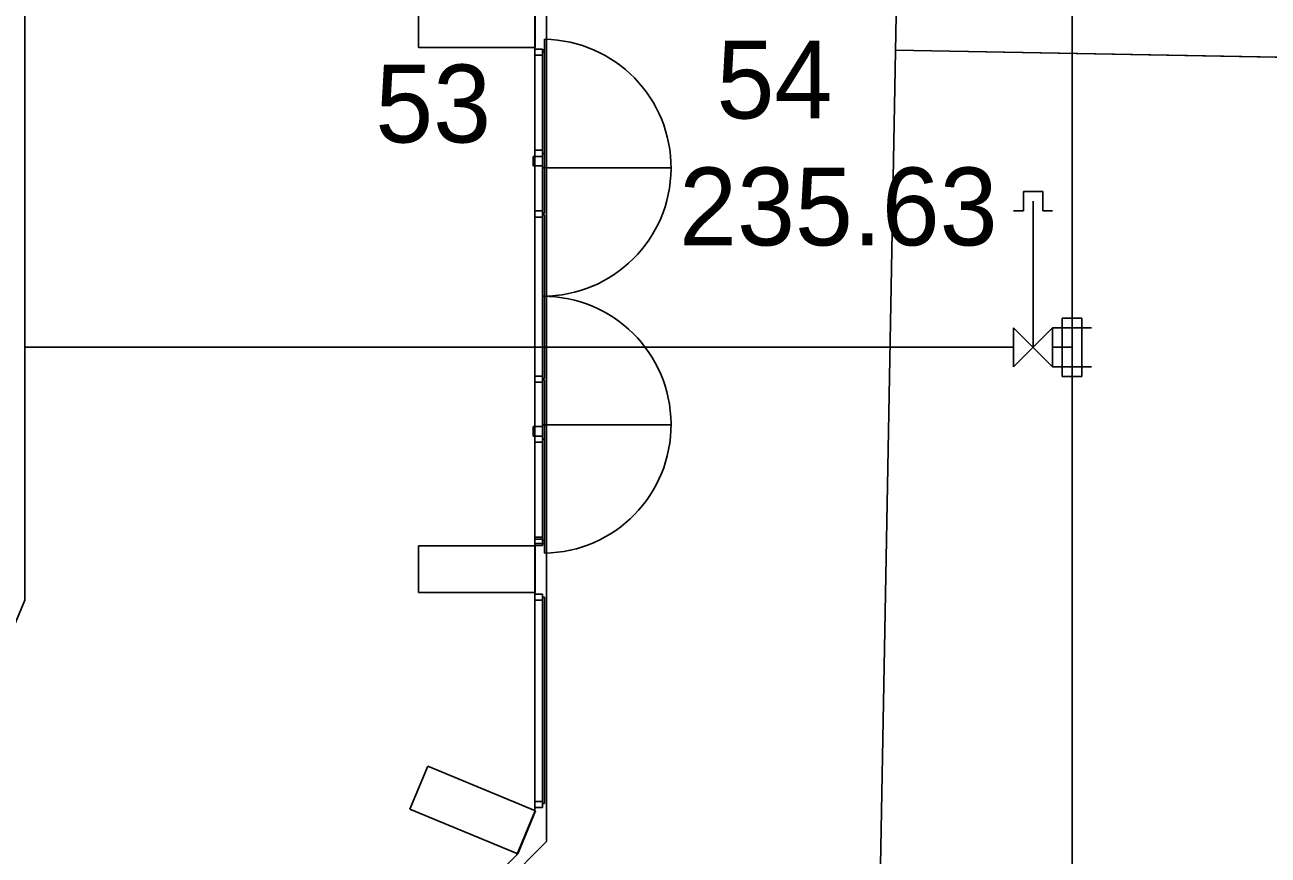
# Model space of a CAD drawing. Extents: x -264234 to -263604, y -1242346 to -1242049.
# Drawn here: x -263801.59 to -263785.62, y -1242227.55 to -1242216.89 of the extents above; entities that cross this region are included whole.
import ezdxf

# ---------------------------------------------------------------- set-up
doc = ezdxf.new("R2010")
doc.units = 0
for name, color, linetype in [('KFA_BODY_CISLO', 7, 'Continuous'), ('KFA_BODY_VYSKA', 7, 'Continuous'), ('KFA_JESTV_IS_DSP_-_KANAL_DAZD', 7, 'Continuous'), ('KFA_SITUACIA_DSP', 7, 'Continuous'), ('KFA_SO_40-2-II_DK_PRIPOJKY_UV_PROJEKT', 7, 'Continuous')]:
    doc.layers.add(name, color=color, linetype=linetype)

msp = doc.modelspace()

# ---------------------------------------------------------------- linework, layer by layer
at = {"layer": 'KFA_JESTV_IS_DSP_-_KANAL_DAZD'}
msp.add_line((-263790.323, -1242212.531), (-263791.054, -1242252.363), dxfattribs=at)
at = {"layer": 'KFA_SITUACIA_DSP'}
for p, q in [((-263788.143, -1242250.14), (-263788.143, -1242082.64)), ((-263795.043, -1242101.769), (-263795.043, -1242226.995)), ((-263796.538, -1242216.582), (-263796.538, -1242217.182)), ((-263795.038, -1242217.182), (-263795.038, -1242216.582)), ((-263796.538, -1242217.182), (-263795.038, -1242217.182)), ((-263795.043, -1242217.282), (-263795.043, -1242217.202)), ((-263795.043, -1242217.202), (-263794.943, -1242217.202)), ((-263795.043, -1242217.282), (-263795.043, -1242217.202)), ((-263795.043, -1242217.202), (-263794.943, -1242217.202)), ((-263794.943, -1242217.202), (-263794.943, -1242217.242)), ((-263794.943, -1242217.202), (-263794.943, -1242217.242)), ((-263794.918, -1242217.212), (-263794.943, -1242217.212)), ((-263794.943, -1242217.212), (-263794.943, -1242219.312)), ((-263794.918, -1242217.077), (-263794.918, -1242218.727)), ((-263794.918, -1242219.312), (-263794.918, -1242217.212)), ((-263781.818, -1242217.375), (-263790.409, -1242217.218)), ((-263794.943, -1242217.282), (-263795.043, -1242217.282)), ((-263794.943, -1242217.282), (-263795.043, -1242217.282)), ((-263794.943, -1242217.242), (-263794.943, -1242217.282)), ((-263794.918, -1242217.242), (-263794.943, -1242217.242)), ((-263794.943, -1242217.242), (-263794.943, -1242218.542)), ((-263794.943, -1242217.242), (-263794.943, -1242217.282)), ((-263794.918, -1242218.542), (-263794.918, -1242217.242)), ((-263795.063, -1242218.702), (-263795.063, -1242218.582)), ((-263795.063, -1242218.582), (-263794.943, -1242218.582)), ((-263794.943, -1242218.502), (-263795.043, -1242218.502)), ((-263795.043, -1242218.502), (-263795.043, -1242218.582)), ((-263795.043, -1242218.582), (-263794.943, -1242218.582)), ((-263794.943, -1242218.542), (-263794.943, -1242218.502)), ((-263794.943, -1242218.542), (-263794.918, -1242218.542)), ((-263794.943, -1242218.582), (-263794.943, -1242218.542)), ((-263794.943, -1242218.582), (-263794.943, -1242218.702)), ((-263794.943, -1242218.702), (-263795.063, -1242218.702)), ((-263794.943, -1242218.702), (-263794.943, -1242218.727)), ((-263794.943, -1242218.727), (-263793.293, -1242218.727)), ((-263788.768, -1242219.032), (-263788.768, -1242219.282)), ((-263788.518, -1242219.032), (-263788.768, -1242219.032)), ((-263788.518, -1242219.282), (-263788.518, -1242219.032)), ((-263795.043, -1242219.362), (-263795.043, -1242219.282)), ((-263795.043, -1242219.282), (-263794.943, -1242219.282)), ((-263794.943, -1242219.282), (-263794.943, -1242219.322)), ((-263788.768, -1242219.282), (-263788.893, -1242219.282)), ((-263788.643, -1242221.032), (-263788.643, -1242219.157)), ((-263788.518, -1242219.282), (-263788.393, -1242219.282)), ((-263794.943, -1242219.362), (-263795.043, -1242219.362)), ((-263794.943, -1242219.312), (-263794.918, -1242219.312)), ((-263794.943, -1242219.322), (-263794.943, -1242219.362)), ((-263794.943, -1242221.432), (-263794.943, -1242219.332)), ((-263794.943, -1242219.332), (-263794.918, -1242219.332)), ((-263794.918, -1242219.332), (-263794.918, -1242221.432)), ((-263788.268, -1242220.657), (-263788.268, -1242221.407)), ((-263788.018, -1242220.657), (-263788.268, -1242220.657)), ((-263788.018, -1242221.407), (-263788.018, -1242220.657)), ((-263788.893, -1242220.782), (-263788.893, -1242221.282)), ((-263788.393, -1242221.282), (-263788.893, -1242220.782)), ((-263788.893, -1242221.282), (-263788.393, -1242220.782)), ((-263788.393, -1242220.782), (-263788.393, -1242221.282)), ((-263788.393, -1242220.782), (-263787.893, -1242220.782)), ((-263801.593, -1242221.032), (-263800.593, -1242221.032)), ((-263788.893, -1242221.032), (-263800.593, -1242221.032)), ((-263788.143, -1242221.032), (-263788.393, -1242221.032)), ((-263788.393, -1242221.032), (-263788.143, -1242221.032)), ((-263788.393, -1242221.282), (-263787.893, -1242221.282)), ((-263795.043, -1242221.482), (-263795.043, -1242221.402)), ((-263795.043, -1242221.402), (-263794.943, -1242221.402)), ((-263794.943, -1242221.482), (-263795.043, -1242221.482)), ((-263794.943, -1242221.402), (-263794.943, -1242221.492)), ((-263794.918, -1242221.432), (-263794.943, -1242221.432)), ((-263794.918, -1242221.452), (-263794.943, -1242221.452)), ((-263794.943, -1242221.452), (-263794.943, -1242223.552)), ((-263794.943, -1242221.492), (-263794.943, -1242221.482)), ((-263794.918, -1242223.552), (-263794.918, -1242221.452)), ((-263788.268, -1242221.407), (-263788.018, -1242221.407)), ((-263794.943, -1242222.052), (-263795.063, -1242222.052)), ((-263795.063, -1242222.052), (-263795.063, -1242222.172)), ((-263794.943, -1242222.052), (-263794.943, -1242222.027)), ((-263794.943, -1242222.027), (-263793.293, -1242222.027)), ((-263794.943, -1242222.172), (-263794.943, -1242222.052)), ((-263794.918, -1242223.677), (-263794.918, -1242222.027)), ((-263795.063, -1242222.172), (-263794.943, -1242222.172)), ((-263795.043, -1242222.252), (-263795.043, -1242222.172)), ((-263795.043, -1242222.172), (-263794.943, -1242222.172)), ((-263794.943, -1242222.252), (-263795.043, -1242222.252)), ((-263794.943, -1242222.172), (-263794.943, -1242222.212)), ((-263794.943, -1242223.512), (-263794.943, -1242222.212)), ((-263794.943, -1242222.212), (-263794.918, -1242222.212)), ((-263794.943, -1242222.212), (-263794.943, -1242222.252)), ((-263794.918, -1242222.212), (-263794.918, -1242223.512)), ((-263795.038, -1242223.582), (-263796.538, -1242223.582)), ((-263796.538, -1242223.582), (-263796.538, -1242224.182)), ((-263794.943, -1242223.472), (-263795.043, -1242223.472)), ((-263795.043, -1242223.472), (-263795.043, -1242223.552)), ((-263794.943, -1242223.497), (-263795.043, -1242223.497)), ((-263795.043, -1242223.497), (-263795.043, -1242223.577)), ((-263795.043, -1242223.552), (-263794.943, -1242223.552)), ((-263795.043, -1242223.577), (-263794.943, -1242223.577)), ((-263795.038, -1242224.182), (-263795.038, -1242223.582)), ((-263794.943, -1242223.512), (-263794.943, -1242223.472)), ((-263794.943, -1242223.537), (-263794.943, -1242223.497)), ((-263794.918, -1242223.512), (-263794.943, -1242223.512)), ((-263794.943, -1242223.552), (-263794.943, -1242223.512)), ((-263794.943, -1242223.577), (-263794.943, -1242223.537)), ((-263794.943, -1242223.552), (-263794.918, -1242223.552)), ((-263796.538, -1242224.182), (-263795.038, -1242224.182)), ((-263795.043, -1242224.282), (-263795.043, -1242224.202)), ((-263795.043, -1242224.202), (-263794.943, -1242224.202)), ((-263794.943, -1242224.202), (-263794.943, -1242224.242)), ((-263794.918, -1242224.242), (-263794.943, -1242224.242)), ((-263794.943, -1242224.242), (-263794.943, -1242226.892)), ((-263794.943, -1242224.242), (-263794.943, -1242224.282)), ((-263794.918, -1242226.892), (-263794.918, -1242224.242)), ((-263794.943, -1242224.282), (-263795.043, -1242224.282)), ((-263796.418, -1242226.411), (-263796.648, -1242226.966)), ((-263795.032, -1242226.985), (-263796.418, -1242226.411)), ((-263795.043, -1242226.945), (-263795.043, -1242226.865)), ((-263795.043, -1242226.865), (-263794.943, -1242226.865)), ((-263794.943, -1242226.945), (-263795.043, -1242226.945)), ((-263794.943, -1242226.865), (-263794.943, -1242226.905)), ((-263794.943, -1242226.892), (-263794.918, -1242226.892)), ((-263794.943, -1242226.905), (-263794.943, -1242226.945)), ((-263796.648, -1242226.966), (-263795.262, -1242227.54)), ((-263795.043, -1242226.995), (-263795.272, -1242227.55)), ((-263795.262, -1242227.54), (-263795.032, -1242226.985)), ((-263795.272, -1242227.55), (-263808.8, -1242241.078))]:
    msp.add_line(p, q, dxfattribs=at)
for points in [[(-263794.893, -1242227.382), (-263808.968, -1242241.457), (-263894.968, -1242241.457), (-263909.043, -1242227.382), (-263909.043, -1242196.333), (-263914.143, -1242196.333), (-263914.143, -1242132.433), (-263909.043, -1242132.433), (-263909.043, -1242101.382), (-263894.968, -1242087.307), (-263808.968, -1242087.307), (-263794.893, -1242101.382), (-263794.893, -1242227.382)], [(-263909.043, -1242125.432), (-263902.343, -1242125.432), (-263902.343, -1242104.482), (-263902.112, -1242103.927), (-263898.54, -1242100.355), (-263895.995, -1242097.81), (-263892.423, -1242094.238), (-263891.868, -1242094.007), (-263812.071, -1242094.007), (-263811.513, -1242094.238), (-263801.823, -1242103.927), (-263801.593, -1242104.482), (-263801.593, -1242224.282), (-263801.824, -1242224.838), (-263805.392, -1242228.407)]]:
    msp.add_lwpolyline(points, dxfattribs=at)
for centre, start, end in [((-263794.943, -1242218.727), 270, 89.1318), ((-263794.943, -1242222.027), 270.8682, 90)]:
    msp.add_arc(centre, 1.65, start, end, dxfattribs=at)
at = {"layer": 'KFA_SO_40-2-II_DK_PRIPOJKY_UV_PROJEKT'}
msp.add_lwpolyline([(-263781.818, -1242217.375), (-263790.409, -1242217.218)], dxfattribs=at)

# ---------------------------------------------------------------- texts
at = {"layer": 'KFA_BODY_CISLO'}
for s, p in [('54', (-263792.709, -1242218.094)), ('53', (-263797.092, -1242218.402))]:
    msp.add_text(s, height=1, dxfattribs=at).set_placement(p)
at = {"layer": 'KFA_BODY_VYSKA'}
msp.add_text('235.63', height=1, dxfattribs=at).set_placement((-263793.189, -1242219.724))

doc.saveas('drawing.dxf')
